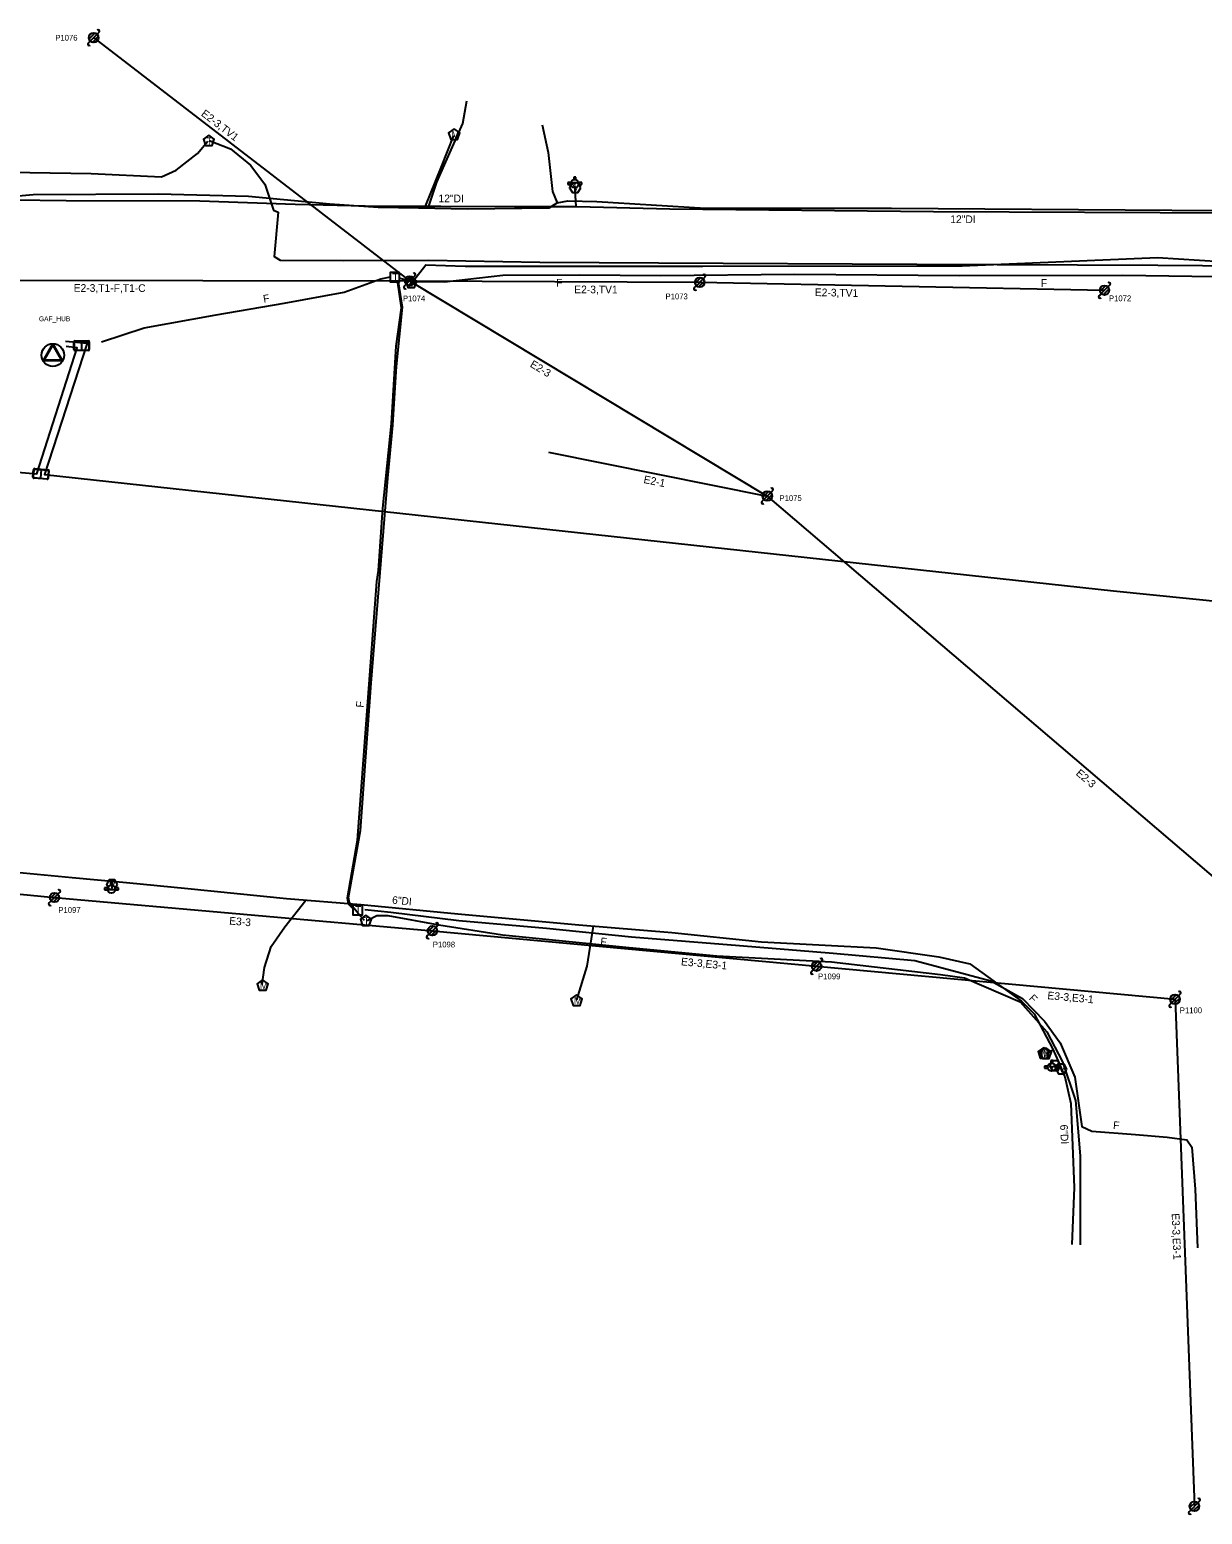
# Model space of a CAD drawing. Extents: x 1614474 to 1865144, y 1098877 to 1212550.
# Drawn here: x 1801769 to 1802379, y 1187603 to 1188375 of the extents above; entities that cross this region are included whole.
import ezdxf

# ---------------------------------------------------------------- set-up
doc = ezdxf.new("R2010")
doc.units = 0
for name, color, linetype in [('BFUSER_BUILDING', 7, 'Continuous'), ('BFUSER_BUILDINGNAME', 7, 'Continuous'), ('BFUSER_DUCTENCLOSURE', 7, 'Continuous'), ('BFUSER_FIBERSPAN', 7, 'Continuous'), ('RD_EX_SU_Gas', 7, 'Continuous'), ('RD_EX_SU_H2O', 7, 'Continuous'), ('RD_EX_SU_Ovhd', 7, 'Continuous'), ('RD_EX_SU_Pole', 7, 'Continuous'), ('RD_EX_SU_Telecom', 7, 'Continuous'), ('RD_EX_SU_TX_H2O', 7, 'Continuous'), ('RD_EX_SU_TX_Pole', 7, 'Continuous'), ('RD_EX_SU_TX_Telecom', 7, 'Continuous')]:
    doc.layers.add(name, color=color, linetype=linetype)

# ---------------------------------------------------------------- blocks, each defined once
blk = doc.blocks.new('SUE_TPP')
at = {"layer": 'RD_EX_SU_Telecom'}
blk.add_lwpolyline([(0, 3), (-2.85, 0.93), (-1.76, -2.43), (1.76, -2.43), (2.85, 0.93)], close=True, dxfattribs=at)
blk.add_text('T', height=3.75, dxfattribs=at).set_placement((-1.25, -1.88))
blk = doc.blocks.new('SUE_WM')
at = {"layer": 'RD_EX_SU_H2O'}
blk.add_lwpolyline([(0, 3.05), (-2.9, 0.94), (-1.79, -2.47), (1.79, -2.47), (2.9, 0.94)], close=True, dxfattribs=at)
blk.add_text('M', height=3.75, dxfattribs=at).set_placement((-1.43, -1.88))
blk = doc.blocks.new('SUE_WV')
at = {"layer": 'RD_EX_SU_H2O'}
blk.add_lwpolyline([(2.89, 0), (1.44, 2.5), (-1.44, 2.5), (-2.89, 0), (-1.44, -2.5), (1.44, -2.5)], close=True, dxfattribs=at)
blk.add_text('V', height=3.75, dxfattribs=at).set_placement((-1.43, -1.88))
blk = doc.blocks.new('SUE_WFH')
at = {"layer": 'RD_EX_SU_H2O'}
for p, q in [((-2.01, 0.6), (-3.65, 0.6)), ((-3.65, 0.6), (-3.65, -0.45)), ((-0.48, 3.38), (-0.48, 2.04)), ((0.57, 3.38), (-0.48, 3.38)), ((0.57, 2.02), (0.57, 3.38)), ((3.7, 0.6), (2.01, 0.6)), ((3.7, -0.45), (3.7, 0.6)), ((-3.65, -0.45), (-2.05, -0.45)), ((2.05, -0.45), (3.7, -0.45))]:
    blk.add_line(p, q, dxfattribs=at)
for radius in [2.1, 0.263]:
    blk.add_circle((0, 0), radius, dxfattribs=at)
for start, end in [(163.3387, 192.31502), (74.24552, 103.21276), (347.68498, 16.6613)]:
    blk.add_arc((0, 0), 2.1, start, end, dxfattribs=at)
blk = doc.blocks.new('SUE_THH')
at = {"layer": 'RD_EX_SU_Telecom'}
blk.add_lwpolyline([(2.5, 2.5), (-2.5, 2.5), (-2.5, -2.5), (2.5, -2.5)], close=True, dxfattribs=at)
blk.add_text('T', height=4, dxfattribs=at).set_placement((-1.34, -2))
blk = doc.blocks.new('SUE_PP')
at = {"layer": 'RD_EX_SU_Pole'}
for p, q in [((-2.41, -0.65), (0.65, 2.41)), ((-1.77, -1.77), (1.77, 1.77)), ((-0.65, -2.41), (2.41, 0.65)), ((1.77, 1.77), (2.83, 2.83)), ((-2.83, -2.83), (-1.77, -1.77))]:
    blk.add_line(p, q, dxfattribs=at)
blk.add_circle((0, 0), 2.5, dxfattribs=at)
for centre, start, end in [((2.3, 3.36), 315, 135), ((-2.3, -3.36), 135, 315)]:
    blk.add_arc(centre, 0.75, start, end, dxfattribs=at)

msp = doc.modelspace()

# ---------------------------------------------------------------- linework, layer by layer
at = {"layer": 'BFUSER_BUILDING'}
for p, q in [((1801775.9, 1188202.74), (1801780.95, 1188211.48)), ((1801776.42, 1188203.04), (1801780.95, 1188210.89)), ((1801780.95, 1188211.48), (1801785.99, 1188202.74)), ((1801780.95, 1188210.89), (1801785.48, 1188203.04)), ((1801785.48, 1188203.04), (1801776.42, 1188203.04)), ((1801778.42, 1188207.11), (1801778.42, 1188207.11)), ((1801783.47, 1188207.11), (1801783.47, 1188207.11)), ((1801785.99, 1188202.74), (1801775.9, 1188202.74)), ((1801780.95, 1188202.74), (1801780.95, 1188202.74))]:
    msp.add_line(p, q, dxfattribs=at)
msp.add_circle((1801780.99, 1188205.7), 5.89, dxfattribs=at)
at = {"layer": 'BFUSER_DUCTENCLOSURE'}
for p, q in [((1801796, 1188212.79), (1801796, 1188208.28)), ((1801775.01, 1188146.12), (1801774.61, 1188141.63))]:
    msp.add_line(p, q, dxfattribs=at)
for points in [[(1801792, 1188208.53), (1801792, 1188212.53)], [(1801792.23, 1188208.68), (1801792.23, 1188212.39)], [(1801792.5, 1188213.03), (1801799.5, 1188213.03)], [(1801792.63, 1188212.79), (1801799.37, 1188212.79)], [(1801799.77, 1188212.39), (1801799.77, 1188208.68)], [(1801800, 1188212.53), (1801800, 1188208.53)], [(1801799.5, 1188208.03), (1801792.5, 1188208.03)], [(1801792.63, 1188208.28), (1801799.37, 1188208.28)], [(1801770.65, 1188142.24), (1801771.01, 1188146.22)], [(1801770.89, 1188142.36), (1801771.23, 1188146.06)], [(1801778.07, 1188141.07), (1801771.1, 1188141.7)], [(1801771.26, 1188141.93), (1801777.96, 1188141.33)], [(1801771.55, 1188146.68), (1801778.52, 1188146.05)], [(1801771.66, 1188146.42), (1801778.37, 1188145.82)], [(1801778.73, 1188145.38), (1801778.4, 1188141.69)], [(1801778.97, 1188145.51), (1801778.62, 1188141.52)]]:
    msp.add_lwpolyline(points, dxfattribs=at)
for centre, radius, start, end in [((1801792.5, 1188212.53), 0.5, 89.99893, 179.99893), ((1801792.63, 1188212.39), 0.4, 89.99893, 179.99893), ((1801799.37, 1188212.39), 0.4, 359.99893, 89.99893), ((1801799.5, 1188212.53), 0.5, 359.99893, 89.99893), ((1801792.5, 1188208.53), 0.5, 179.99893, 269.99893), ((1801792.63, 1188208.68), 0.4, 179.99893, 269.99893), ((1801799.37, 1188208.68), 0.4, 269.99893, 359.99893), ((1801799.5, 1188208.53), 0.5, 269.99893, 359.99893), ((1801771.15, 1188142.19), 0.5, 174.87267, 264.87267), ((1801771.29, 1188142.33), 0.4, 174.87267, 264.87267), ((1801771.5, 1188146.18), 0.5, 84.87267, 174.87267), ((1801771.62, 1188146.02), 0.4, 84.87267, 174.87267), ((1801778, 1188141.73), 0.4, 264.87267, 354.87267), ((1801778.12, 1188141.57), 0.5, 264.87267, 354.87267), ((1801778.33, 1188145.42), 0.4, 354.87267, 84.87267), ((1801778.48, 1188145.55), 0.5, 354.87267, 84.87267)]:
    msp.add_arc(centre, radius, start, end, dxfattribs=at)
at = {"layer": 'BFUSER_FIBERSPAN'}
for points in [[(1800084.25, 1188303.4), (1800779.19, 1188255.87), (1800833.78, 1188281.15), (1801076.57, 1188204.5), (1801772.73, 1188143.98), (1801793.73, 1188209.4), (1801787.99, 1188210.07)], [(1801787.69, 1188212.97), (1801798.88, 1188211.88), (1801776.62, 1188143.66), (1802332.91, 1188082.99), (1802687.07, 1188047.3), (1802985.23, 1188050.78), (1803198.95, 1188076.24)]]:
    msp.add_lwpolyline(points, dxfattribs=at)
at = {"layer": 'RD_EX_SU_Gas'}
for points in [[(1801976.25, 1188282.13), (1801980.73, 1188295.55), (1801994.29, 1188326.19), (1801996.46, 1188337.93)], [(1802035.69, 1188325.53), (1802038.75, 1188311.1), (1802040.95, 1188290.73), (1802043.42, 1188284.85), (1802048.92, 1188285.96), (1802064.02, 1188285.5), (1802120.55, 1188282.05), (1802217.43, 1188282.09), (1802363.14, 1188281), (1802531.2, 1188280.89), (1802592.84, 1188280.65), (1802657.49, 1188281.38), (1802745.41, 1188285.57)], [(1801300.18, 1188289.75), (1801395.65, 1188290.16), (1801455.8, 1188291.53), (1801513.04, 1188289.66), (1801598.92, 1188288.81), (1801632.69, 1188288.87), (1801670.37, 1188289.16), (1801709.24, 1188288.32), (1801749.77, 1188287.36), (1801770.8, 1188289.23), (1801835.8, 1188289.57), (1801882.8, 1188288.37), (1801925.16, 1188284.33), (1801950.2, 1188282.64), (1801971.28, 1188282.21), (1801996.82, 1188281.83), (1802039.19, 1188282.29), (1802043.42, 1188284.85)]]:
    msp.add_lwpolyline(points, dxfattribs=at)
at = {"layer": 'RD_EX_SU_H2O'}
for p, q in [((1802052.46, 1188293.86), (1802053.04, 1188283.22)), ((1801811.94, 1187932.03), (1801811.71, 1187928.55)), ((1802297.91, 1187842.36), (1802301.39, 1187844.31)), ((1802304.72, 1187836.97), (1802301.07, 1187835.36))]:
    msp.add_line(p, q, dxfattribs=at)
for points in [[(1801974.9, 1188283.19), (1801982.97, 1188303.2), (1801989.64, 1188319.96)], [(1801299.98, 1188292.06), (1801348.52, 1188291.53), (1801396.06, 1188291.83), (1801455.82, 1188292.39), (1801499.16, 1188291.09), (1801533.71, 1188290.84), (1801614.7, 1188290.73), (1801629.95, 1188291.7), (1801670.47, 1188290.08), (1801698.41, 1188288.36), (1801733.35, 1188286.84), (1801787.88, 1188286.07), (1801857.46, 1188285.91)], [(1801857.46, 1188285.91), (1801907.01, 1188284.1), (1801950.85, 1188283.21), (1801982.92, 1188283.18), (1802021.22, 1188283.03), (1802053.57, 1188283.05), (1802102.06, 1188281.72), (1802239.26, 1188280.4), (1802593.05, 1188278.81), (1802731.51, 1188277.72), (1802853.5, 1188276.84), (1802894.3, 1188276.72), (1802928.34, 1188277.44), (1802964.61, 1188277.33), (1802990.65, 1188277.72), (1803038.29, 1188278.47)], [(1801725.3, 1187940.21), (1801791.08, 1187933.95), (1801819.37, 1187931.34), (1801851.29, 1187928.17), (1801902.56, 1187923.1), (1801941.32, 1187919.89), (1801991.7, 1187915.14), (1802054.62, 1187909.36), (1802103.14, 1187905.32), (1802149.67, 1187900.43), (1802209.38, 1187897.3), (1802242.04, 1187892.68), (1802258.1, 1187889), (1802284.97, 1187869.65), (1802291.6, 1187863.04), (1802301.1, 1187844.94), (1802304.23, 1187838.11), (1802307.56, 1187830.34), (1802310.63, 1187816.46), (1802312.45, 1187772.68), (1802311.13, 1187743.09)], [(1801889.94, 1187878.24), (1801891.06, 1187887.18), (1801894.69, 1187898.08), (1801901.75, 1187908.26), (1801912.64, 1187922.26)], [(1802053.72, 1187870.38), (1802059.06, 1187887.79), (1802062.28, 1187908.73)]]:
    msp.add_lwpolyline(points, dxfattribs=at)
at = {"layer": 'RD_EX_SU_Ovhd'}
for p, q in [((1801802.26, 1188370.75), (1801966.65, 1188244.29)), ((1801740.09, 1188244.68), (1801966.65, 1188244.29)), ((1801966.65, 1188244.29), (1802152.75, 1188132.38)), ((1801966.65, 1188244.29), (1802117.6, 1188243.55)), ((1802117.6, 1188243.55), (1802328.18, 1188239.42)), ((1802038.84, 1188155.18), (1802152.75, 1188132.38)), ((1802152.75, 1188132.38), (1802473.88, 1187858.09)), ((1801589.05, 1187942), (1801781.89, 1187923.55)), ((1801781.89, 1187923.55), (1801978.51, 1187906.27)), ((1801978.51, 1187906.27), (1802178.38, 1187887.81)), ((1802178.38, 1187887.81), (1802364.88, 1187870.6)), ((1802364.88, 1187870.6), (1802374.98, 1187606.9))]:
    msp.add_line(p, q, dxfattribs=at)
at = {"layer": 'RD_EX_SU_Pole'}
for p, q in [((1801963.82, 1188241.46), (1801964.88, 1188242.52)), ((1801964.24, 1188243.64), (1801967.3, 1188246.7)), ((1801964.88, 1188242.52), (1801968.42, 1188246.06)), ((1801966, 1188241.87), (1801969.07, 1188244.94)), ((1801968.42, 1188246.06), (1801969.48, 1188247.12)), ((1802114.77, 1188240.72), (1802115.83, 1188241.78)), ((1802115.18, 1188242.9), (1802118.24, 1188245.97)), ((1802115.83, 1188241.78), (1802119.36, 1188245.32)), ((1802116.95, 1188241.14), (1802120.01, 1188244.2)), ((1802119.36, 1188245.32), (1802120.42, 1188246.38)), ((1802150.33, 1188131.74), (1802153.39, 1188134.8)), ((1802150.98, 1188130.61), (1802154.51, 1188134.15)), ((1802154.51, 1188134.15), (1802155.57, 1188135.21)), ((1802149.92, 1188129.55), (1802150.98, 1188130.61)), ((1802152.1, 1188129.97), (1802155.16, 1188133.03)), ((1801779.47, 1187922.9), (1801782.53, 1187925.96)), ((1801780.12, 1187921.78), (1801783.65, 1187925.32)), ((1801783.65, 1187925.32), (1801784.71, 1187926.38)), ((1801779.06, 1187920.72), (1801780.12, 1187921.78)), ((1801781.24, 1187921.13), (1801784.3, 1187924.2)), ((1801975.68, 1187903.44), (1801976.74, 1187904.5)), ((1801976.09, 1187905.62), (1801979.15, 1187908.68)), ((1801976.74, 1187904.5), (1801980.28, 1187908.03)), ((1801977.86, 1187903.85), (1801980.92, 1187906.91)), ((1801980.28, 1187908.03), (1801981.34, 1187909.09)), ((1802175.97, 1187887.16), (1802179.03, 1187890.22)), ((1802176.62, 1187886.04), (1802180.15, 1187889.57)), ((1802177.74, 1187885.39), (1802180.8, 1187888.45)), ((1802180.15, 1187889.57), (1802181.21, 1187890.64)), ((1802175.55, 1187884.98), (1802176.62, 1187886.04)), ((1802362.46, 1187869.96), (1802365.53, 1187873.02)), ((1802363.11, 1187868.83), (1802366.65, 1187872.37)), ((1802364.23, 1187868.19), (1802367.29, 1187871.25)), ((1802366.65, 1187872.37), (1802367.71, 1187873.43)), ((1802362.05, 1187867.77), (1802363.11, 1187868.83))]:
    msp.add_line(p, q, dxfattribs=at)
for centre in [(1801966.65, 1188244.29), (1802117.6, 1188243.55), (1802152.75, 1188132.38), (1801781.89, 1187923.55), (1801978.51, 1187906.27), (1802178.38, 1187887.81), (1802364.88, 1187870.6)]:
    msp.add_circle(centre, 2.5, dxfattribs=at)
for centre, start, end in [((1801964.35, 1188240.93), 135, 315), ((1801968.95, 1188247.65), 315, 135), ((1802119.89, 1188246.91), 315, 135), ((1802115.3, 1188240.19), 135, 315), ((1802155.04, 1188135.74), 315, 135), ((1802150.45, 1188129.02), 135, 315), ((1801784.18, 1187926.91), 315, 135), ((1801779.59, 1187920.19), 135, 315), ((1801980.81, 1187909.62), 315, 135), ((1801976.21, 1187902.91), 135, 315), ((1802180.68, 1187891.17), 315, 135), ((1802176.08, 1187884.45), 135, 315), ((1802367.18, 1187873.96), 315, 135), ((1802362.58, 1187867.24), 135, 315)]:
    msp.add_arc(centre, 0.75, start, end, dxfattribs=at)
at = {"layer": 'RD_EX_SU_Telecom'}
for p, q in [((1801962.96, 1188230.57), (1801960.8, 1188243.81)), ((1801965.75, 1188244.36), (1801961.24, 1188245.76)), ((1801959.86, 1188199.71), (1801962.96, 1188230.57)), ((1801957.91, 1188169.31), (1801959.86, 1188199.71)), ((1801955.33, 1188141.64), (1801957.91, 1188169.31)), ((1801946.71, 1188034.96), (1801955.33, 1188141.64)), ((1801941.14, 1187958.4), (1801946.71, 1188034.96)), ((1801934.87, 1187923.59), (1801941.14, 1187958.4))]:
    msp.add_line(p, q, dxfattribs=at)
for points in [[(1801655.86, 1188347.6), (1801655.95, 1188329.98), (1801657.97, 1188328.39), (1801682.15, 1188336.73), (1801696.88, 1188334.16), (1801702.52, 1188318.42), (1801706.09, 1188310.43), (1801716.39, 1188304.98), (1801729.28, 1188302.18), (1801747.59, 1188301.03), (1801801.04, 1188300.2), (1801837.59, 1188298.33), (1801845.25, 1188301.81), (1801856.3, 1188310.58), (1801861.71, 1188317.02)], [(1801862.35, 1188317.37), (1801873.43, 1188312.99), (1801883.86, 1188304.45), (1801891.39, 1188294.55), (1801895.78, 1188281.09), (1801898.32, 1188280.05), (1801896.15, 1188256.89), (1801899.35, 1188255.07), (1801932.38, 1188254.92), (1801976.57, 1188255.02), (1802034.35, 1188254.03), (1802096.1, 1188253.61), (1802230.47, 1188252.94), (1802355.95, 1188252.37), (1802518.32, 1188251.31), (1802574.51, 1188250.38), (1802659.53, 1188249.82), (1802718.99, 1188248.54), (1802800.77, 1188248.26), (1802860.92, 1188247.72), (1802867.92, 1188245.53), (1802871.84, 1188241.03), (1802871.83, 1188230.11)], [(1801968.17, 1188243.8), (1801975.11, 1188252.56), (1801995.47, 1188251.98), (1802119.14, 1188251.93), (1802254.07, 1188252.11), (1802355.76, 1188256.39), (1802454.16, 1188250.22), (1802615.38, 1188248.45), (1802660.58, 1188248.77), (1802719.54, 1188247.91), (1802781.2, 1188247.75), (1802841.08, 1188246.91), (1802917.35, 1188246.59), (1802979.82, 1188247.18), (1803040.76, 1188247.99), (1803094.59, 1188247.87), (1803108.84, 1188247.38), (1803112.58, 1188243.21)], [(1801806.38, 1188212.57), (1801828.6, 1188219.82), (1801866.07, 1188226.7), (1801901.39, 1188232.66), (1801932.6, 1188238.34), (1801951.69, 1188245.35), (1801956.77, 1188246.33)], [(1801937.44, 1187917.57), (1801934.88, 1187920.04), (1801934.31, 1187923.33), (1801939.57, 1187953.46), (1801949.62, 1188087.86), (1801950.43, 1188093.68), (1801952.68, 1188125.99), (1801957.13, 1188170.02), (1801959.71, 1188210.28), (1801962.5, 1188230.28), (1801960.31, 1188244.49)], [(1801967.37, 1188243.92), (1801984.85, 1188243.7), (1802015.11, 1188247.25), (1802055.06, 1188247.37), (1802097.38, 1188247.06), (1802166.97, 1188247.83), (1802252.78, 1188247.03), (1802337.76, 1188247.32), (1802433.59, 1188245.79), (1802518.24, 1188245.41), (1802614.63, 1188244.32), (1802677.58, 1188242.3), (1802718.6, 1188243.19), (1802760.44, 1188243.9), (1802821.17, 1188242.63), (1802859.98, 1188240.47), (1802897.26, 1188239.34), (1802946.24, 1188239.68), (1802991.69, 1188241.06), (1803061.1, 1188241.67)], [(1801943.15, 1187911.68), (1801940.05, 1187915.08), (1801935.43, 1187920.72), (1801934.87, 1187923.59)], [(1801943.26, 1187917.31), (1801956.92, 1187915.93), (1801992.21, 1187911.53), (1802037.78, 1187907.69), (1802082.02, 1187903.16), (1802138.34, 1187898.66), (1802186.93, 1187894.54), (1802229.54, 1187890.84), (1802268.97, 1187880.25), (1802285.55, 1187871.03), (1802296.96, 1187859.25), (1802305.18, 1187847.93), (1802312.74, 1187830.07), (1802316.39, 1187804.37), (1802321.63, 1187802.03), (1802344.38, 1187800.31), (1802360.84, 1187798.96), (1802371, 1187797.45), (1802373.6, 1187793.77), (1802375.28, 1187771.94), (1802376.6, 1187741.29)], [(1801944.47, 1187911.54), (1801949.56, 1187914.18), (1801955.28, 1187914.2), (1801981.85, 1187909.26), (1802014.93, 1187904.08), (1802080.82, 1187897.51), (1802126.41, 1187893.16), (1802186.18, 1187890.03), (1802242.93, 1187883.44), (1802255.33, 1187881.83), (1802284.32, 1187869.29), (1802298.2, 1187853.66), (1802306.27, 1187838.08), (1802313.08, 1187817.98), (1802315.58, 1187789.19), (1802315.54, 1187742.93)]]:
    msp.add_lwpolyline(points, dxfattribs=at)

# ---------------------------------------------------------------- block references
at = {"layer": 'RD_EX_SU_H2O'}
for name, p in [('SUE_WM', (1801989.81, 1188320.35)), ('SUE_WFH', (1802052.53, 1188294.87)), ('SUE_WV', (1802052.8, 1188292.74)), ('SUE_WV', (1801811.77, 1187930.27)), ('SUE_WFH', (1801811.48, 1187927.93)), ('SUE_WM', (1801890.15, 1187877.76)), ('SUE_WM', (1802053.5, 1187869.85)), ('SUE_WM', (1802296.57, 1187842.45)), ('SUE_WM', (1802297.66, 1187842.34)), ('SUE_WFH', (1802300.68, 1187835.32)), ('SUE_WV', (1802302.49, 1187836.1)), ('SUE_WV', (1802305.75, 1187834.34))]:
    msp.add_blockref(name, p, dxfattribs=at)
at = {"layer": 'RD_EX_SU_Pole'}
for p in [(1801802.26, 1188370.75), (1802328.18, 1188239.42), (1802374.98, 1187606.9)]:
    msp.add_blockref('SUE_PP', p, dxfattribs=at)
at = {"layer": 'RD_EX_SU_Telecom'}
for name, p in [('SUE_TPP', (1801862.17, 1188317.04)), ('SUE_THH', (1801958.95, 1188246.21)), ('SUE_TPP', (1801967.46, 1188243.22)), ('SUE_THH', (1801939.58, 1187917.07)), ('SUE_TPP', (1801943.9, 1187911.44))]:
    msp.add_blockref(name, p, dxfattribs=at)

# ---------------------------------------------------------------- texts
at = {"layer": 'BFUSER_BUILDINGNAME'}
msp.add_text('GAF_HUB', height=2.5, dxfattribs=at).set_placement((1801773.78, 1188223.3))
at = {"layer": 'RD_EX_SU_Ovhd'}
for s, rotation, p in [('E2-3,TV1', 322.43088, (1801857.83, 1188330.53)), ('E2-3,T1-F,T1-C', 359.90156, (1801791.85, 1188238.59)), ('E2-3,TV1', 359.71986, (1802052.28, 1188237.87)), ('E2-3,TV1', 358.87692, (1802177.43, 1188236.38)), ('E2-3', 328.97973, (1802028.92, 1188199.85)), ('E2-1', 348.6846, (1802088.12, 1188139.2)), ('E2-3', 319.4977, (1802312.96, 1187987.65)), ('E3-3', 354.97657, (1801872.65, 1187909.55)), ('E3-3,E3-1', 354.72348, (1802107.7, 1187888.31)), ('E3-3,E3-1', 354.72927, (1802298.35, 1187870.71)), ('E3-3,E3-1', 272.19301, (1802363.14, 1187759.22))]:
    msp.add_text(s, height=4, rotation=rotation, dxfattribs=at).set_placement(p)
at = {"layer": 'RD_EX_SU_TX_H2O'}
for s, rotation, p in [('12"DI', 359.77683, (1801981.66, 1188285.18)), ('12"DI', 359.74357, (1802247.92, 1188274.36)), ('6"DI', 354.6207, (1801957.38, 1187920.38)), ('6"DI', 272.37936, (1802305.09, 1187805.37))]:
    msp.add_text(s, height=4, rotation=rotation, dxfattribs=at).set_placement(p)
at = {"layer": 'RD_EX_SU_TX_Pole'}
for s, p in [('P1076', (1801782.27, 1188369.24)), ('P1074', (1801963.14, 1188233.65)), ('P1073', (1802099.77, 1188234.71)), ('P1072', (1802330.49, 1188233.71)), ('P1075', (1802159.06, 1188129.8)), ('P1097', (1801783.89, 1187915.57)), ('P1098', (1801978.71, 1187897.6)), ('P1099', (1802179.15, 1187881.02)), ('P1100', (1802367.35, 1187863.38))]:
    msp.add_text(s, height=3, dxfattribs=at).set_placement(p)
at = {"layer": 'RD_EX_SU_TX_Telecom'}
for rotation, p in [(0.177, (1802042.86, 1188241.33)), (0.19749, (1802295.02, 1188241.18)), (9.58546, (1801890.78, 1188232.9)), (85.72311, (1801942.7, 1188022.22)), (354.15346, (1802065.71, 1187898.8)), (314.07868, (1802288.55, 1187870.81)), (355.67593, (1802332.52, 1187803.21))]:
    msp.add_text('F', height=4, rotation=rotation, dxfattribs=at).set_placement(p)

doc.saveas('drawing.dxf')
